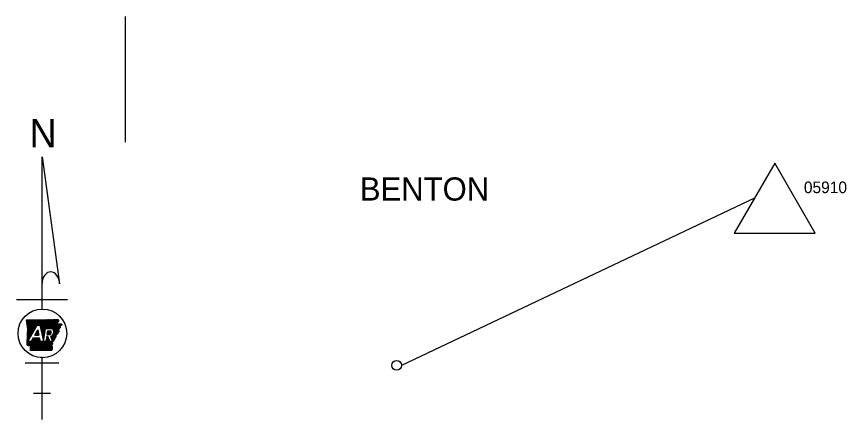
# Model space of a CAD drawing. Extents: x -35254 to 17396, y -8913 to 11592.
# Drawn here: x -35254 to -26670, y 7085 to 11258 of the extents above; entities that cross this region are included whole.
import ezdxf

# ---------------------------------------------------------------- set-up
doc = ezdxf.new("R2010")
doc.units = 0
for name, color, linetype in [('2', 7, 'Continuous'), ('R_Annotation', 7, 'Continuous'), ('R_No Plot', 7, 'Continuous')]:
    doc.layers.add(name, color=color, linetype=linetype)

msp = doc.modelspace()

# ---------------------------------------------------------------- linework, layer by layer
at = {"layer": 'R_Annotation'}
for p, q in [((-34126.5, 9955.1), (-34126.5, 11257.8)), ((-34991.2, 9804.3), (-34809.4, 8490.2)), ((-34991.2, 8228.4), (-34991.2, 9804.3)), ((-27411.6, 9738.2), (-27829.5, 9014.3)), ((-26993.6, 9014.3), (-27411.6, 9738.2)), ((-27620.5, 9376.2), (-31272.8, 7645)), ((-27829.5, 9014.3), (-26993.6, 9014.3)), ((-35254.4, 8325.8), (-34728.1, 8325.8)), ((-35150.9, 8115.5), (-35148.7, 8117.7)), ((-35150.1, 8109.3), (-35141.7, 8117.7)), ((-35149.3, 8103.1), (-35134.8, 8117.7)), ((-35148.5, 8097), (-35127.8, 8117.7)), ((-35147.8, 8090.8), (-35120.8, 8117.7)), ((-35147, 8084.6), (-35113.9, 8117.7)), ((-35146.2, 8078.4), (-35106.9, 8117.7)), ((-35145.5, 8072.2), (-35100, 8117.7)), ((-35144.7, 8066), (-35093, 8117.7)), ((-35143.9, 8059.8), (-35086, 8117.7)), ((-35143.1, 8053.6), (-35079.1, 8117.7)), ((-35142.4, 8047.4), (-35072.1, 8117.7)), ((-35141.6, 8041.2), (-35065.2, 8117.7)), ((-35140.8, 8035), (-35058.2, 8117.7)), ((-35140.6, 7965.6), (-34988.4, 8117.8)), ((-35140.4, 7972.8), (-34995.4, 8117.8)), ((-35140.1, 7980), (-35002.4, 8117.8)), ((-35140.1, 8028.8), (-35051.2, 8117.7)), ((-35139.9, 7987.2), (-35009.3, 8117.7)), ((-35139.6, 7994.4), (-35016.3, 8117.7)), ((-35139.4, 8001.6), (-35023.3, 8117.7)), ((-35139.3, 8022.6), (-35044.2, 8117.7)), ((-35139.2, 8008.8), (-35030.3, 8117.7)), ((-35138.9, 8016), (-35037.3, 8117.7)), ((-35037.2, 8062.1), (-34981.4, 8117.8)), ((-35030.2, 8062.1), (-34974.4, 8117.8)), ((-35023.2, 8062.1), (-34967.4, 8117.9)), ((-35016.3, 8062.1), (-34960.3, 8118)), ((-35011.9, 8059.4), (-34953.3, 8118.1)), ((-35010.7, 8053.7), (-34946.2, 8118.2)), ((-35009.5, 8048), (-34939.1, 8118.3)), ((-35008.2, 8042.2), (-34932, 8118.4)), ((-35007, 8036.5), (-34925, 8118.5)), ((-35005.8, 8030.7), (-34917.9, 8118.6)), ((-35004.6, 8025), (-34910.8, 8118.8)), ((-35003.3, 8019.3), (-34903.7, 8118.9)), ((-35002.1, 8013.5), (-34896.7, 8119)), ((-35000.9, 8007.8), (-34889.6, 8119.1)), ((-34999.6, 8002.1), (-34882.5, 8119.2)), ((-34998.4, 7996.3), (-34875.4, 8119.3)), ((-34997.2, 7990.6), (-34868.3, 8119.4)), ((-34996, 7984.8), (-34861.2, 8119.6)), ((-34947.6, 8026.3), (-34854.1, 8119.8)), ((-34940.6, 8026.3), (-34846.9, 8119.9)), ((-34933.6, 8026.3), (-34839.8, 8120.1)), ((-34926.7, 8026.3), (-34832.7, 8120.3)), ((-34919.7, 8026.3), (-34825.5, 8120.4)), ((-34912.7, 8026.3), (-34824, 8115)), ((-34905.8, 8026.3), (-34820.6, 8111.4)), ((-34898.8, 8026.3), (-34819.7, 8105.4)), ((-34891.8, 8026.3), (-34835.6, 8082.5)), ((-34885.5, 8025.6), (-34837, 8074.1)), ((-34881.7, 8022.5), (-34829.7, 8074.5)), ((-34878.3, 8018.9), (-34822.3, 8074.9)), ((-34875.3, 8014.9), (-34815, 8075.3)), ((-34872.7, 8010.6), (-34807.6, 8075.7)), ((-34870.6, 8005.7), (-34800.3, 8076)), ((-34869, 8000.4), (-34793.7, 8075.7)), ((-34868, 7994.3), (-34790.4, 8072)), ((-35141.8, 7929.6), (-35083.2, 7988.1)), ((-35141.6, 7936.8), (-35074.1, 8004.2)), ((-35141.3, 7944), (-35065, 8020.3)), ((-35141.1, 7951.2), (-35055.9, 8036.3)), ((-35140.8, 7958.4), (-35046.8, 8052.4)), ((-35138.5, 7890.5), (-35041.4, 8062.1)), ((-35067, 7957.8), (-35035.3, 8013.9)), ((-35066.7, 7957.8), (-35030.9, 7993.6)), ((-35059.7, 7957.8), (-35029.7, 7987.9)), ((-35058.4, 7973.1), (-35032.1, 7999.3)), ((-35049.3, 7989.2), (-35033.4, 8005.1)), ((-35041.4, 8062.1), (-35012.5, 8062.1)), ((-35040.2, 8005.2), (-35034.6, 8010.8)), ((-34994.7, 7979.1), (-34955.2, 8018.6)), ((-34993.5, 7973.4), (-34956.7, 8010.2)), ((-34992.3, 7967.6), (-34958.1, 8001.8)), ((-34991, 7961.9), (-34959.6, 7993.3)), ((-34989.8, 7956.2), (-34961.1, 7984.9)), ((-34953.9, 8026.3), (-34886.4, 8026.3)), ((-34939.2, 7965.4), (-34902.5, 8002)), ((-34937.8, 7973.8), (-34909.5, 8002)), ((-34936.3, 7982.2), (-34916.5, 8002)), ((-34934.8, 7990.7), (-34923.4, 8002)), ((-34933.4, 7999.1), (-34930.4, 8002)), ((-34932.8, 8002), (-34901.2, 8002)), ((-34932.2, 7965.4), (-34898.7, 7999)), ((-34925.3, 7965.4), (-34896.3, 7994.3)), ((-34918.3, 7965.4), (-34895, 7988.7)), ((-34898.2, 7936.3), (-34821, 8013.5)), ((-34896.3, 7931.2), (-34819.7, 8007.9)), ((-34894.5, 7926.1), (-34818.4, 8002.2)), ((-34892.6, 7921), (-34817.1, 7996.5)), ((-34875.5, 7966), (-34822.3, 8019.2)), ((-34869.5, 7979), (-34806.2, 8042.2)), ((-34868, 7987.4), (-34807, 8048.4)), ((-34814, 8027.4), (-34805.4, 8036.1)), ((-34793.5, 8061.9), (-34787.2, 8068.3)), ((-35143, 7893.5), (-35128.7, 7907.8)), ((-35142.8, 7900.7), (-35119.6, 7923.9)), ((-35142.5, 7908), (-35110.5, 7940)), ((-35142.3, 7915.2), (-35101.4, 7956)), ((-35142, 7922.4), (-35092.3, 7972.1)), ((-35141.5, 7853.3), (-35068.3, 7926.5)), ((-35137.3, 7850.4), (-35061.3, 7926.5)), ((-35132.3, 7848.5), (-35054.3, 7926.5)), ((-35124.1, 7849.8), (-35047.4, 7926.5)), ((-35117, 7849.9), (-35040.4, 7926.5)), ((-35111.5, 7848.4), (-35033.4, 7926.5)), ((-35111.3, 7834.7), (-35019.5, 7926.5)), ((-35111.3, 7841.6), (-35026.5, 7926.5)), ((-35111.3, 7827.7), (-35015.8, 7923.2)), ((-35111.2, 7820.8), (-35014.6, 7917.4)), ((-35111.2, 7813.9), (-35013.4, 7911.7)), ((-35111.2, 7806.9), (-35012.2, 7906)), ((-35111.1, 7800.1), (-35010.9, 7900.2)), ((-35084.8, 7926.5), (-35105.2, 7890.5)), ((-35097.3, 7904.4), (-35075.2, 7926.5)), ((-35088.2, 7920.5), (-35082.2, 7926.5)), ((-35016.5, 7926.5), (-35084.8, 7926.5)), ((-35067, 7957.8), (-35023.3, 7957.8)), ((-35052.8, 7957.8), (-35028.5, 7982.1)), ((-35045.8, 7957.8), (-35027.2, 7976.4)), ((-35041.5, 7799.9), (-34921.7, 7919.7)), ((-35038.8, 7957.8), (-35026, 7970.7)), ((-35034.6, 7799.9), (-34919.9, 7914.7)), ((-35031.9, 7957.8), (-35024.8, 7964.9)), ((-35027.6, 7799.9), (-34918, 7909.6)), ((-35024.9, 7957.8), (-35023.5, 7959.2)), ((-35020.7, 7799.9), (-34916.1, 7904.5)), ((-35013.7, 7799.9), (-34914.2, 7899.4)), ((-34988.6, 7950.4), (-34962.6, 7976.5)), ((-34987.4, 7944.7), (-34964, 7968)), ((-34986.1, 7938.9), (-34965.5, 7959.6)), ((-34984.9, 7933.2), (-34967, 7951.1)), ((-34983.7, 7927.5), (-34968.4, 7942.7)), ((-34982.5, 7921.7), (-34969.9, 7934.3)), ((-34981.2, 7916), (-34971.4, 7925.8)), ((-34980, 7910.3), (-34972.8, 7917.4)), ((-34978.8, 7904.5), (-34974.3, 7909)), ((-34977.5, 7898.8), (-34975.8, 7900.5)), ((-34951.1, 7897.4), (-34923.6, 7924.8)), ((-34949.6, 7905.8), (-34925.5, 7929.9)), ((-34948.1, 7914.2), (-34927.4, 7935)), ((-34946.7, 7922.7), (-34929.3, 7940.1)), ((-34945.2, 7931.1), (-34931.3, 7945)), ((-34943.7, 7939.5), (-34938.2, 7945)), ((-34931.1, 7945), (-34942.8, 7945)), ((-34939.2, 7965.4), (-34910.3, 7965.4)), ((-34910.9, 7890.5), (-34931.1, 7945)), ((-34911.3, 7965.4), (-34895.6, 7981.1)), ((-34902.5, 7947.9), (-34881.3, 7890.5)), ((-34902, 7946.5), (-34899.9, 7948.6)), ((-34900.1, 7941.4), (-34886.8, 7954.6)), ((-34890.7, 7916), (-34848.9, 7957.7)), ((-34888.8, 7910.9), (-34849.7, 7950)), ((-34886.9, 7905.8), (-34850.5, 7942.2)), ((-34885.1, 7900.7), (-34863.7, 7922.1)), ((-34883.2, 7895.6), (-34866.7, 7912.1)), ((-34840.9, 7965.8), (-34831.1, 7975.5)), ((-35144.1, 7857.6), (-35111.2, 7890.5)), ((-35143.9, 7864.7), (-35118.2, 7890.5)), ((-35143.7, 7871.9), (-35125.2, 7890.5)), ((-35143.5, 7879.1), (-35132.1, 7890.5)), ((-35143.2, 7886.3), (-35137.8, 7891.8)), ((-35105.2, 7890.5), (-35138.5, 7890.5)), ((-35104.1, 7800), (-35009.7, 7894.5)), ((-35097.2, 7800), (-35006.8, 7890.5)), ((-35090.2, 7800), (-34999.8, 7890.5)), ((-35083.3, 7800), (-34992.8, 7890.5)), ((-35076.3, 7800), (-34985.9, 7890.5)), ((-35069.4, 7800), (-34978.9, 7890.5)), ((-35062.4, 7800), (-34971.9, 7890.5)), ((-35055.5, 7800), (-34965, 7890.5)), ((-35048.5, 7800), (-34958, 7890.5)), ((-34952.3, 7890.5), (-35008.8, 7890.5)), ((-35006.8, 7799.9), (-34912.3, 7894.3)), ((-34999.8, 7799.9), (-34909.2, 7890.5)), ((-34992.9, 7799.9), (-34902.3, 7890.5)), ((-34985.9, 7799.8), (-34895.3, 7890.5)), ((-34979, 7799.8), (-34888.3, 7890.5)), ((-34972, 7799.8), (-34886, 7885.8)), ((-34965.1, 7799.8), (-34885.7, 7879.2)), ((-34958.1, 7799.8), (-34885.4, 7872.5)), ((-34951.1, 7799.8), (-34885.1, 7865.9)), ((-34944.2, 7799.8), (-34896.5, 7847.5)), ((-34937.2, 7799.8), (-34894.4, 7842.6)), ((-34930.3, 7799.8), (-34892.2, 7837.8)), ((-34923.3, 7799.7), (-34890.1, 7833)), ((-34916.4, 7799.7), (-34887.9, 7828.2)), ((-34881.3, 7890.5), (-34910.9, 7890.5)), ((-34909.4, 7799.7), (-34886.1, 7823)), ((-34902.5, 7799.7), (-34889.3, 7812.9)), ((-34895.5, 7799.7), (-34892.4, 7802.8)), ((-35166.6, 7670), (-34815.8, 7670)), ((-34991.2, 7084.7), (-34991.2, 7724.3)), ((-35079, 7358.4), (-34903.5, 7358.4))]:
    msp.add_line(p, q, dxfattribs=at)
for points in [[(-35151.1, 8117.7), (-35055.1, 8117.6), (-34970.7, 8117.8), (-34871.2, 8119.4), (-34825.1, 8120.4)], [(-35151.1, 8117.7), (-35055, 8117.6), (-34970.7, 8117.8), (-34871.2, 8119.4), (-34825.1, 8120.4)], [(-35140.5, 7968.3), (-35138.8, 8018.9), (-35151.1, 8117.7)], [(-35144.2, 7857.7), (-35138.8, 8018.9), (-35151.1, 8117.7)], [(-34794.9, 8076.3), (-34786.6, 8067.6), (-34807.3, 8050.6), (-34805.1, 8033.4), (-34822.9, 8021.6), (-34816.8, 7995.2), (-34830.5, 7982.7), (-34831.7, 7969.1), (-34848.4, 7963.1), (-34851, 7937.4), (-34862.9, 7924.6), (-34868.7, 7905.3), (-34886.2, 7889.3), (-34884.8, 7861.2), (-34896.7, 7847.9), (-34885.9, 7823.7), (-34893.4, 7799.7)], [(-34839.4, 8074.1), (-34794.3, 8076.3)], [(-34839.4, 8074), (-34794.2, 8076.3)], [(-35035.3, 8013.9), (-35023.3, 7957.8)], [(-35012.5, 8062.1), (-34976.7, 7895), (-34953.9, 8026.3)], [(-34939.2, 7965.4), (-34932.8, 8002)], [(-35144.2, 7857.7), (-35140.5, 7968.3)], [(-35008.8, 7890.5), (-35016.5, 7926.5)], [(-34942.8, 7945), (-34952.3, 7890.5)], [(-34893.4, 7799.7), (-35111.2, 7800.1), (-35111.3, 7848.1)], [(-34893.4, 7799.7), (-35111.2, 7800.1), (-35111.3, 7848.1)]]:
    msp.add_lwpolyline(points, dxfattribs=at)
msp.add_circle((-31322.8, 7645), 50, dxfattribs=at)
for centre, major_axis, ratio, start_param, end_param in [((-34900.4, 8487.3), (-3.9, 126.3), 0.719778, 4.712385, 7.768526), ((-34917.2, 7986.6), (-22.3, 0), 0.999987, 1.887169, 3.90762), ((-34911.5, 7990.6), (-43.6, 0), 0.999987, 1.777838, 4.099264)]:
    msp.add_ellipse(centre, major_axis=major_axis, ratio=ratio, start_param=start_param, end_param=end_param, dxfattribs=at)
msp.add_ellipse((-34987.1, 7976.4), major_axis=(252.1, 0), ratio=0.999976, dxfattribs=at)
for points in [[(-34825.1, 8120.4), (-34824.8, 8117.8), (-34824, 8116.5), (-34823.9, 8114), (-34822.8, 8112.9), (-34821.1, 8111.8), (-34819.6, 8110.1), (-34819.2, 8108.1), (-34819.7, 8106), (-34819.8, 8103.6), (-34820, 8101.6), (-34820.4, 8099.8), (-34821.8, 8098.3), (-34823.2, 8097.3), (-34824.4, 8096.1), (-34825.3, 8094.7), (-34826.9, 8093.3), (-34828.4, 8091.8), (-34829.7, 8090.5), (-34830.9, 8088.8), (-34831.5, 8087), (-34832.9, 8085.7), (-34834, 8084.5), (-34835.4, 8082.9), (-34836.1, 8081.3), (-34837.4, 8079.4), (-34837.8, 8077.7), (-34838.6, 8076.3), (-34838.7, 8076)], [(-34825.1, 8120.4), (-34824.8, 8117.8), (-34824, 8116.5), (-34823.8, 8114), (-34822.8, 8112.9), (-34821.1, 8111.8), (-34819.6, 8110.1), (-34819.2, 8108.1), (-34819.7, 8106), (-34819.8, 8103.7), (-34820, 8101.7), (-34820.4, 8099.8), (-34821.8, 8098.3), (-34823.2, 8097.3), (-34824.4, 8096), (-34825.3, 8094.7), (-34826.9, 8093.3), (-34828.4, 8091.8), (-34829.7, 8090.5), (-34830.9, 8088.8), (-34831.5, 8087), (-34832.9, 8085.7), (-34833.9, 8084.5), (-34835.4, 8082.9), (-34836.1, 8081.3), (-34837.5, 8079.4), (-34837.8, 8077.7), (-34838.6, 8076.2), (-34838.7, 8076)], [(-34794.9, 8076.3), (-34794.3, 8076.3), (-34792.2, 8074.2), (-34791.4, 8072.4), (-34790, 8071.4), (-34788.5, 8070.9), (-34787.4, 8069.5), (-34786.7, 8068), (-34787.1, 8066.7), (-34788.7, 8066.6), (-34790.6, 8066.3), (-34792.4, 8066.4), (-34793.8, 8065.1), (-34792.5, 8063.6), (-34790.7, 8062.1), (-34790.3, 8060.5), (-34791.2, 8059), (-34793.1, 8058.1), (-34795, 8057.4), (-34796.6, 8056), (-34797.4, 8054.6), (-34799.3, 8054), (-34801.1, 8053.5), (-34802.8, 8053.3), (-34804.7, 8052.9), (-34806.5, 8052), (-34807.3, 8050.5), (-34807.1, 8048.3), (-34807.1, 8046), (-34805.2, 8045.2), (-34803.5, 8045.1), (-34801.8, 8044.3), (-34802, 8043), (-34803.2, 8041.3), (-34804.7, 8040), (-34806.2, 8039.3), (-34807.6, 8038.1), (-34807.1, 8036.8), (-34805.8, 8036), (-34805, 8034.6), (-34805.1, 8033.4), (-34806.5, 8032.5), (-34808, 8032.9), (-34809.2, 8034.3), (-34810.5, 8034.8), (-34811.6, 8035.3), (-34812.9, 8034.6), (-34812.9, 8032.9), (-34813.4, 8031), (-34813, 8029.7), (-34812.5, 8027.7), (-34812.5, 8026.3), (-34813, 8024.3), (-34814, 8022.2), (-34815.1, 8021.6), (-34815.7, 8023.8), (-34815.9, 8025.6), (-34816.6, 8026.7), (-34817.6, 8026.8), (-34818.8, 8025.9), (-34820.2, 8024.5), (-34821.9, 8023), (-34822.9, 8021.6), (-34822.3, 8019.7), (-34821.1, 8019.3), (-34820, 8019.6), (-34819.5, 8020.8), (-34818.6, 8020.9), (-34817.6, 8019.1)], [(-34817.6, 8019.1), (-34817.3, 8017.4), (-34818.3, 8015.6), (-34818.7, 8013.7), (-34818.6, 8011.9), (-34820.4, 8010.9), (-34822.1, 8009.7), (-34821.1, 8008.2), (-34819.3, 8006.9), (-34817.6, 8005.9), (-34816.5, 8004.9), (-34816.1, 8002.5), (-34815.8, 8000.9), (-34815.2, 7998.8), (-34815, 7997.3), (-34816.1, 7995.5), (-34817.3, 7995.2), (-34818.6, 7995.6), (-34820.2, 7995.7), (-34821.4, 7994.5), (-34822.3, 7992.8), (-34823.2, 7991.2), (-34823.9, 7989.8), (-34824.5, 7988.2), (-34825.8, 7986.4), (-34827.4, 7986.1), (-34829.3, 7985.6), (-34830.5, 7984.4), (-34830.2, 7982.1), (-34829.2, 7980.7), (-34828.4, 7978.8), (-34827.8, 7977.2), (-34828, 7975.2), (-34828.9, 7973.7), (-34830, 7972.8), (-34830.5, 7970.9), (-34831.2, 7969.5), (-34831.9, 7969), (-34833.4, 7969.1), (-34834.9, 7969.4), (-34836.2, 7969.3), (-34837.4, 7968.7), (-34838.7, 7969.1), (-34840, 7970.5), (-34841.1, 7971.6), (-34842.3, 7972), (-34843.5, 7971.3), (-34843.7, 7969.4), (-34843.1, 7967.3), (-34842.6, 7964.6), (-34843.1, 7963), (-34843.3, 7960.2)], [(-34876.3, 7903.9), (-34876.4, 7903.9), (-34877.5, 7902.5), (-34876.9, 7900.4), (-34874.6, 7899.6), (-34873.5, 7897.6), (-34873.5, 7895.8), (-34874.2, 7893.4), (-34875.3, 7892.2), (-34877.4, 7891.7), (-34879, 7891.5), (-34879.2, 7888.7), (-34880, 7887.4), (-34881.2, 7887), (-34883, 7887.8), (-34884.1, 7888.3), (-34885.4, 7888.9), (-34887, 7889.8), (-34888.3, 7889.7), (-34887.9, 7887.1), (-34887.8, 7887), (-34886.4, 7885), (-34885, 7883.4), (-34884.3, 7881.6)], [(-34876.3, 7903.9), (-34876.4, 7903.9), (-34877.5, 7902.5), (-34876.9, 7900.4), (-34874.6, 7899.6), (-34873.5, 7897.6), (-34873.5, 7895.8), (-34874.2, 7893.4), (-34875.3, 7892.2), (-34877.4, 7891.7), (-34879, 7891.5), (-34879.2, 7888.7), (-34880, 7887.4), (-34881.2, 7887), (-34883, 7887.8), (-34884.1, 7888.3), (-34885.4, 7888.9), (-34887, 7889.8), (-34888.3, 7889.7), (-34887.9, 7887.1), (-34887.8, 7887), (-34886.4, 7885), (-34885, 7883.4), (-34884.3, 7881.6)], [(-34843.3, 7960.2), (-34845.4, 7958.6), (-34846.4, 7957), (-34851.6, 7957.5), (-34851.5, 7955.6), (-34853.4, 7954.6), (-34855, 7953.4), (-34854.1, 7952), (-34852.3, 7950.7), (-34850.5, 7949.7), (-34849.4, 7948.7), (-34849.1, 7946.2), (-34848.8, 7944.7), (-34848.2, 7942.5), (-34848, 7941.1), (-34849, 7939.3), (-34850.3, 7938.9), (-34851.6, 7939.4), (-34853.1, 7939.5), (-34854.4, 7938.3), (-34855.3, 7936.6), (-34856.1, 7934.9), (-34856.8, 7933.5), (-34857.5, 7932), (-34858.8, 7930.2), (-34860.4, 7929.9), (-34862.3, 7929.4), (-34863.4, 7928.1), (-34863.2, 7925.9), (-34862.2, 7924.4), (-34861.3, 7922.6), (-34860.8, 7921), (-34861, 7919), (-34861.8, 7917.4), (-34862.9, 7916.6), (-34863.4, 7914.7), (-34864.2, 7913.2), (-34864.9, 7912.8), (-34866.3, 7912.9), (-34867.9, 7913.2), (-34869.2, 7913.1), (-34870.4, 7912.4), (-34871.7, 7912.8), (-34873, 7914.3), (-34874.1, 7915.3), (-34875.2, 7915.8), (-34876.5, 7915.1), (-34876.7, 7913.1), (-34876.1, 7911.1), (-34875.6, 7908.4), (-34876.1, 7906.7), (-34876.3, 7903.9)], [(-35111.3, 7848.1), (-35111.1, 7848), (-35112.2, 7848.8), (-35113.7, 7849.6), (-35115.5, 7849.7), (-35117.7, 7850), (-35119.5, 7850.1), (-35121.4, 7851.4), (-35123.4, 7850.1), (-35125.7, 7849.1), (-35127, 7850.2), (-35128.7, 7849.5), (-35129.9, 7849.9), (-35132, 7848.4), (-35134, 7849), (-35135.4, 7848.6), (-35137.1, 7848.6), (-35137.5, 7850.6), (-35139.3, 7850.9), (-35140.7, 7851.8), (-35141.7, 7853.8), (-35142.5, 7855.5), (-35144.2, 7857.7)], [(-35111.3, 7848.1), (-35111.1, 7848), (-35112.2, 7848.8), (-35113.7, 7849.6), (-35115.5, 7849.7), (-35117.7, 7850), (-35119.5, 7850.2), (-35121.4, 7851.4), (-35123.4, 7850.1), (-35125.7, 7849.1), (-35127, 7850.2), (-35128.7, 7849.5), (-35129.9, 7849.9), (-35132, 7848.4), (-35134, 7849), (-35135.4, 7848.5), (-35137.2, 7848.6), (-35137.5, 7850.6), (-35139.2, 7850.9), (-35140.7, 7851.8), (-35141.7, 7853.8), (-35142.5, 7855.4), (-35144.2, 7857.7)], [(-34884.3, 7881.6), (-34884.9, 7880.2), (-34885.6, 7877.8), (-34885.4, 7875.8), (-34884.4, 7874.1), (-34883.1, 7873.2), (-34881.5, 7871.8), (-34881.6, 7869.7), (-34882.5, 7869), (-34884.6, 7869.4), (-34886.2, 7870.2), (-34887.6, 7869.8), (-34889.4, 7868.9), (-34890.8, 7868.7), (-34890.7, 7865.8), (-34888.9, 7863.8), (-34887.3, 7863.8), (-34885.4, 7863.6), (-34884.8, 7861.4), (-34885.8, 7859.6), (-34887.6, 7858.8), (-34889.9, 7859.9), (-34891.5, 7861), (-34893.1, 7862), (-34895.1, 7862.6), (-34896.2, 7862.4), (-34896.8, 7859.9), (-34895.8, 7857.6), (-34894.3, 7856), (-34892.9, 7854), (-34893.1, 7852.5), (-34894.1, 7852.1), (-34896.1, 7851.7), (-34897.2, 7851.1), (-34897.5, 7850.6), (-34896.9, 7848.6), (-34896.4, 7846.4), (-34896.4, 7844.7), (-34897, 7843.2), (-34898, 7840.9), (-34897.9, 7839.3), (-34897.2, 7838.6), (-34896.3, 7838.8), (-34895.1, 7839.6), (-34894.3, 7840.6), (-34893.7, 7841.8), (-34892.4, 7842.8), (-34890.9, 7841.9), (-34890.5, 7840.1), (-34891.4, 7838.5), (-34892.7, 7837.7), (-34894.2, 7837.1), (-34895.3, 7835.8), (-34895.1, 7834.3), (-34894.1, 7833.4), (-34891.9, 7833.9), (-34890.5, 7834.5), (-34889.6, 7835.3), (-34888.6, 7836.4), (-34888.1, 7837.4), (-34887.3, 7838.5), (-34885.9, 7838.8), (-34885.3, 7837.9), (-34885.6, 7835.8), (-34886.4, 7833.9), (-34887.5, 7832.3), (-34888.7, 7831.2), (-34890.3, 7828.8), (-34890, 7826.5), (-34889.4, 7824.6), (-34888.6, 7823.2), (-34887.1, 7823.5), (-34885.6, 7823.7), (-34884.6, 7822.9), (-34884.7, 7821.3), (-34885.9, 7819.6), (-34887, 7818.1), (-34887.6, 7816), (-34887.4, 7814.5), (-34887.4, 7813.2), (-34887.8, 7811.6), (-34888.7, 7810.8), (-34890.9, 7810.8), (-34893.2, 7811.1), (-34894.4, 7810.4), (-34894.2, 7808.4), (-34892.9, 7806.9), (-34891.9, 7806.1), (-34890.5, 7804.4), (-34889.9, 7803.1), (-34890.1, 7801.9), (-34891, 7800.8), (-34893.4, 7799.7)], [(-34884.3, 7881.6), (-34884.9, 7880.2), (-34885.6, 7877.8), (-34885.4, 7875.8), (-34884.4, 7874.1), (-34883.1, 7873.2), (-34881.5, 7871.8), (-34881.6, 7869.7), (-34882.5, 7869), (-34884.6, 7869.4), (-34886.2, 7870.2), (-34887.6, 7869.8), (-34889.4, 7868.9), (-34890.8, 7868.7), (-34890.7, 7865.8), (-34888.9, 7863.8), (-34887.3, 7863.8), (-34885.4, 7863.6), (-34884.8, 7861.4), (-34885.8, 7859.6), (-34887.6, 7858.8), (-34889.9, 7859.9), (-34891.5, 7861), (-34893.1, 7862), (-34895.1, 7862.6), (-34896.2, 7862.4), (-34896.8, 7859.9), (-34895.8, 7857.6), (-34894.3, 7856), (-34892.9, 7854), (-34893.1, 7852.5), (-34894.1, 7852.1), (-34896.1, 7851.7), (-34897.2, 7851.1), (-34897.5, 7850.6), (-34896.9, 7848.6), (-34896.4, 7846.4), (-34896.4, 7844.7), (-34897, 7843.2), (-34898, 7840.9), (-34897.9, 7839.3), (-34897.2, 7838.6), (-34896.3, 7838.8), (-34895.1, 7839.6), (-34894.3, 7840.6), (-34893.7, 7841.8), (-34892.4, 7842.8), (-34890.9, 7841.9), (-34890.5, 7840.1), (-34891.4, 7838.5), (-34892.7, 7837.7), (-34894.2, 7837.1), (-34895.3, 7835.8), (-34895.1, 7834.3), (-34894.1, 7833.4), (-34891.9, 7833.9), (-34890.5, 7834.5), (-34889.6, 7835.3), (-34888.6, 7836.4), (-34888.1, 7837.4), (-34887.3, 7838.5), (-34885.9, 7838.8), (-34885.3, 7837.9), (-34885.6, 7835.8), (-34886.4, 7833.9), (-34887.5, 7832.3), (-34888.7, 7831.2), (-34890.3, 7828.8), (-34890, 7826.5), (-34889.4, 7824.6), (-34888.6, 7823.2), (-34887.1, 7823.5), (-34885.6, 7823.7), (-34884.6, 7822.9), (-34884.7, 7821.3), (-34885.9, 7819.6), (-34887, 7818.1), (-34887.6, 7816), (-34887.4, 7814.5), (-34887.4, 7813.2), (-34887.8, 7811.6), (-34888.7, 7810.8), (-34890.9, 7810.8), (-34893.2, 7811.1), (-34894.4, 7810.4), (-34894.2, 7808.4), (-34892.9, 7806.9), (-34891.9, 7806.1), (-34890.5, 7804.4), (-34889.9, 7803.1), (-34890.1, 7801.9), (-34891, 7800.8), (-34893.4, 7799.7)]]:
    msp.add_spline(points, degree=3, dxfattribs=at)

# ---------------------------------------------------------------- texts
at = {"layer": '2'}
msp.add_text('BENTON', height=240, dxfattribs=at).set_placement((-31703.2, 9351.7))
at = {"layer": 'R_Annotation'}
for s, height, p in [('N', 293.3, (-35122, 9903.5)), ('STS 10-03-17', 7.288, (-35011.2, 7726.4))]:
    msp.add_text(s, height=height, dxfattribs=at).set_placement(p)
at = {"layer": 'R_No Plot'}
msp.add_text('05910', height=120, dxfattribs=at).set_placement((-27109.7, 9429))

doc.saveas('drawing.dxf')
